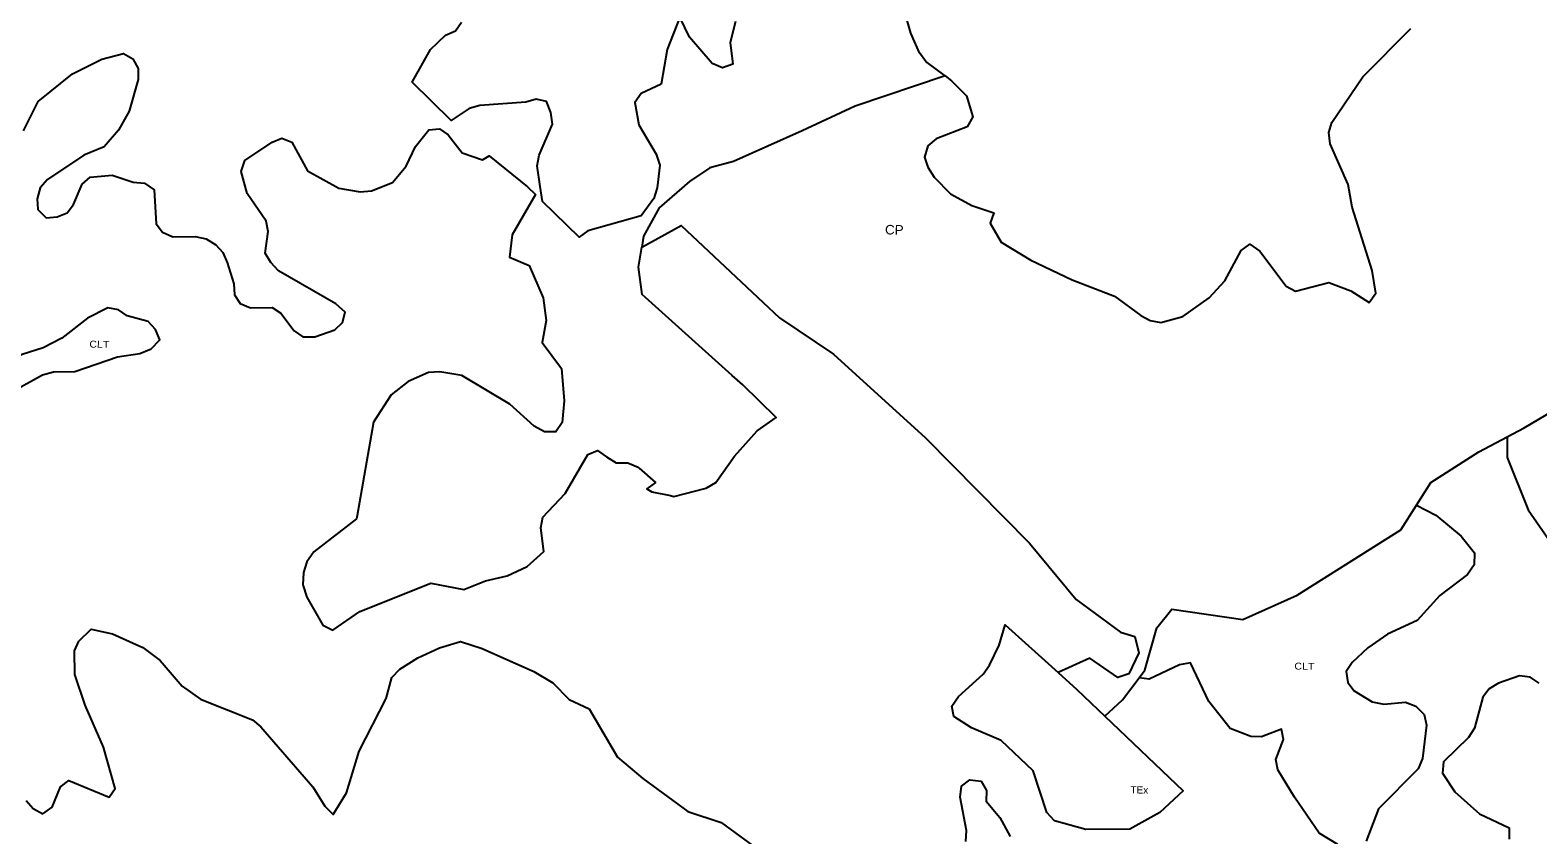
# Model space of a CAD drawing. Extents: x 713589 to 726391, y 7177764 to 7191819.
# Drawn here: x 716445 to 717458, y 7180995 to 7181536 of the extents above; entities that cross this region are included whole.
import ezdxf
from ezdxf.enums import TextEntityAlignment as Align

# ---------------------------------------------------------------- set-up
doc = ezdxf.new("R2010")
doc.units = 0
doc.header["$LTSCALE"] = 2.6
doc.layers.add('63', color=7, linetype='Continuous', lineweight=25)

msp = doc.modelspace()

# ---------------------------------------------------------------- linework, layer by layer
at = {"layer": '63'}
for points in [[(716919.05, 7181541.67), (716915.43, 7181527.52), (716917.07, 7181513.04), (716910.16, 7181510.41), (716903.25, 7181513.37), (716888.12, 7181531.15), (716881.54, 7181544.64), (716872.98, 7181522.92), (716869.03, 7181499.56), (716855.53, 7181493.31), (716851.25, 7181487.06), (716853.88, 7181472.25), (716865.73, 7181452.5), (716868.03, 7181444.93), (716866.38, 7181429.8), (716864.08, 7181422.56), (716855.52, 7181411.04), (716819.65, 7181400.85), (716813.81, 7181396.58), (716789.24, 7181420.53), (716787.69, 7181430.77), (716785.6, 7181444.55), (716786.93, 7181451.81), (716795.87, 7181472.57), (716794.89, 7181480.49), (716791.94, 7181487.76), (716785.01, 7181489.42), (716778.08, 7181487.45), (716747.07, 7181485.19), (716739.81, 7181483.22), (716727.79, 7181474.97), (716701.66, 7181500.8), (716713.81, 7181522.85), (716724.06, 7181532.4), (716730.66, 7181535.36), (716734.63, 7181541.29)], [(717059.92, 7181505.01), (717047.06, 7181514.66), (717042.78, 7181520.59), (717036.86, 7181533.75), (717032.58, 7181548.56)], [(717059.92, 7181505.01), (717064.17, 7181501.83), (717074.36, 7181491.63), (717078.64, 7181477.47), (717074.69, 7181470.89), (717053.96, 7181462.67), (717048.36, 7181458.06), (717046.06, 7181450.5), (717048.36, 7181443.59), (717052.64, 7181437), (717063.49, 7181425.81), (717077.97, 7181417.91), (717092.78, 7181412.97), (717090.15, 7181406.06), (717097.71, 7181393.23), (717117.45, 7181381.05), (717145.42, 7181367.88), (717173.72, 7181357.02), (717191.49, 7181343.85), (717197.74, 7181340.56), (717204.98, 7181339.24), (717219.79, 7181343.19), (717237.56, 7181355.69), (717248.09, 7181367.21), (717258.96, 7181387.61), (717264.88, 7181391.88), (717271.46, 7181387.28), (717289.23, 7181363.58), (717295.48, 7181360.29), (717317.86, 7181366.21), (717332.66, 7181360.61), (717345.17, 7181352.71), (717349.44, 7181358.96), (717347.14, 7181374.1), (717333.66, 7181416.88), (717331.03, 7181432.02), (717318.86, 7181459.33), (717317.87, 7181466.9), (717319.85, 7181473.81), (717340.91, 7181504.41), (717373.17, 7181536.98)], [(716440.24, 7181468.18), (716450.12, 7181487.92), (716473.16, 7181506.34), (716492.9, 7181516.21), (716507.38, 7181520.16), (716513.63, 7181516.54), (716517.25, 7181509.95), (716517.25, 7181502.71), (716511.32, 7181481.33), (716504.08, 7181468.49), (716494.54, 7181457.31), (716480.71, 7181451.71), (716456.36, 7181435.27), (716451.42, 7181429.67), (716449.45, 7181422.43), (716449.78, 7181415.19), (716455.37, 7181409.6), (716462.94, 7181410.25)], [(717059.92, 7181505.01), (716999.53, 7181484.73), (716963.77, 7181468.01), (716917.6, 7181447.53), (716901.79, 7181443.28), (716887.97, 7181434.07), (716867.56, 7181416.3), (716857.03, 7181397.22), (716855.88, 7181389.95)], [(716462.94, 7181410.25), (716469.52, 7181412.89), (716473.8, 7181418.48), (716479.72, 7181432.3), (716484.99, 7181436.91), (716499.8, 7181438.22), (716513.95, 7181433.61), (716521.52, 7181432.95), (716528.1, 7181428.34), (716529.41, 7181405.64), (716533.69, 7181400.04), (716540.6, 7181396.75), (716555.73, 7181397.08), (716562.97, 7181395.43), (716569.55, 7181391.48), (716574.16, 7181386.21), (716577.12, 7181379.63), (716581.72, 7181365.15), (716582.05, 7181357.91), (716586, 7181351.99), (716592.91, 7181349.02), (716607.39, 7181349.35), (716613.31, 7181345.4), (716622.19, 7181333.55), (716628.12, 7181329.6), (716636.01, 7181329.6), (716649.51, 7181334.21), (716654.77, 7181339.14), (716656.42, 7181346.05), (716650.17, 7181351.65), (716611.67, 7181374.03), (716606.41, 7181379.63), (716602.79, 7181385.88), (716604.77, 7181400.36), (716603.45, 7181407.27), (716590.62, 7181426.03), (716586.67, 7181440.84), (716588.98, 7181448.08), (716607.41, 7181460.58), (716613.99, 7181463.21), (716620.57, 7181460.57), (716631.1, 7181441.16), (716652.16, 7181429.64), (716666.64, 7181427), (716674.2, 7181427.66), (716688.36, 7181433.25), (716697.57, 7181444.44), (716703.83, 7181457.6), (716712.71, 7181468.79), (716719.95, 7181469.44), (716725.87, 7181465.49), (716735.09, 7181453.32), (716748.91, 7181448.71), (716753.43, 7181451.35), (716779.05, 7181430.47), (716784.45, 7181425.2), (716768.7, 7181398.07), (716767.02, 7181383.23), (716780.21, 7181377.6), (716789.74, 7181355.81), (716791.69, 7181340.63), (716789.03, 7181325.79), (716801.86, 7181308.29), (716803.81, 7181286.51), (716802.46, 7181272), (716798.17, 7181265.74), (716790.58, 7181265.75), (716783.66, 7181269.39), (716767.19, 7181284.26), (716734.89, 7181303.45), (716720.05, 7181306.11), (716712.46, 7181305.47), (716698.93, 7181299.55), (716687.37, 7181290.66), (716675.46, 7181272.21), (716664.52, 7181209.42), (716664.14, 7181207.24), (716635.4, 7181184.86), (716630.77, 7181178.27), (716628.45, 7181171.02), (716628.11, 7181162.77), (716630.73, 7181154.52), (716641.59, 7181135.7), (716648.18, 7181132.39), (716666.35, 7181144.89), (716714.21, 7181163.95), (716736.3, 7181159.62), (716750.83, 7181165.54), (716765.35, 7181168.81), (716778.88, 7181175.05), (716790.12, 7181185.26), (716788.16, 7181201.1), (716789.49, 7181208.35), (716804.36, 7181224.16)], [(716855.88, 7181389.95), (716882.5, 7181404.46), (716948.63, 7181342.25), (716984.83, 7181317.89), (717046.68, 7181261.61), (717116.76, 7181190.85), (717148.02, 7181153), (717177.96, 7181130.95), (717187.5, 7181127.98), (717190.13, 7181117.12), (717183.55, 7181102.97), (717180.16, 7181101.79), (717175.98, 7181100.34), (717157.22, 7181113.51), (717135.97, 7181103.74)], [(716804.36, 7181224.16), (716819.58, 7181250.53), (716826.18, 7181253.16), (716832.12, 7181248.86), (716838.71, 7181244.89), (716846.62, 7181244.88), (716853.55, 7181241.9), (716854.25, 7181241.28), (716865.26, 7181231.54), (716859.39, 7181227.3), (716862.73, 7181225.25), (716875.19, 7181222.75), (716877.53, 7181222.28), (716899.25, 7181227.87), (716905.84, 7181231.49), (716918.34, 7181249.26), (716933.48, 7181266.37), (716946.33, 7181275.25), (716923.81, 7181297.17), (716916.64, 7181303.63), (716856.2, 7181358.09), (716853.74, 7181376.49), (716855.88, 7181389.95)], [(717437.8, 7181262.38), (717449.33, 7181268.45), (717489.81, 7181292.46), (717596.72, 7181346.37)], [(717376.94, 7181216.44), (717386.48, 7181231.6), (717418.73, 7181252.33), (717437.8, 7181262.38)], [(717437.8, 7181262.38), (717437.95, 7181248.38), (717452.09, 7181213.17), (717485.97, 7181164.13)], [(717190.46, 7181100.3), (717194.28, 7181105.28), (717202.18, 7181133.9), (717212.38, 7181146.41), (717260.1, 7181139.49), (717296.63, 7181155.93), (717366.4, 7181199.69), (717376.94, 7181216.44)], [(717376.94, 7181216.44), (717389.89, 7181209.56), (717407, 7181195.4), (717415.89, 7181184.21), (717415.56, 7181176.32), (717411.28, 7181169.73), (717392.52, 7181155.59), (717377.38, 7181138.81), (717357.3, 7181129.6), (717344.14, 7181120.39), (717333.61, 7181110.52), (717329.66, 7181104.59), (717330.64, 7181097.02), (717334.92, 7181091.43), (717347.09, 7181084.19), (717354.99, 7181082.54), (717369.47, 7181083.85), (717376.38, 7181081.22), (717381.97, 7181075.63), (717383.62, 7181068.39), (717380.98, 7181046.01), (717378.02, 7181039.1), (717351.36, 7181012.12), (717343.13, 7180990.4)], [(717167.37, 7181074.45), (717219.98, 7181024.17), (717204.26, 7181009.65), (717184.19, 7180998.46), (717154.57, 7180998.14), (717133.51, 7181004.06), (717128.25, 7181009.66), (717119.04, 7181037.63), (717097.65, 7181058.04), (717077.58, 7181066.6), (717065.74, 7181074.17), (717064.42, 7181081.08), (717069.03, 7181087.66), (717085.49, 7181102.79), (717089.76, 7181108.72), (717096.35, 7181122.21), (717100.26, 7181135.84), (717135.97, 7181103.74)], [(716441.9, 7181017.81), (716446.79, 7181012.33), (716453.09, 7181008.67), (716459.39, 7181013.3), (716465.05, 7181026.88), (716470.69, 7181031.18), (716497.84, 7181019.86), (716501.83, 7181025.82), (716493.92, 7181053.67), (716481.71, 7181081.86), (716474.78, 7181102.42), (716474.48, 7181118.33), (716477.47, 7181124.96), (716485.71, 7181132.99), (716500.07, 7181129.88), (716520.47, 7181120.66), (716531.99, 7181111.78), (716546.8, 7181094.66), (716559.3, 7181085.77), (716594.18, 7181071.95), (716599.77, 7181067.34), (716634.65, 7181026.86), (716642.87, 7181014.02)], [(716642.87, 7181014.02), (716648.36, 7181008.26), (716653.8, 7181017.12), (716657.35, 7181022.9), (716665.91, 7181050.87), (716684.02, 7181086.41), (716687.97, 7181100.56), (716693.23, 7181106.15), (716705.41, 7181113.72), (716719.89, 7181120.3), (716734.04, 7181124.57), (716748.52, 7181119.96), (716783.4, 7181104.49), (716796.23, 7181096.92), (716807.09, 7181085.73), (716820.58, 7181079.48), (716839.66, 7181046.89), (716856.77, 7181032.41), (716886.95, 7181010.24), (716909.28, 7181002.98), (716946.13, 7180975.99)], [(717324.04, 7180988.1), (717311.54, 7180995.67), (717294.76, 7181020.03), (717283.57, 7181038.46), (717282.26, 7181045.37), (717287.53, 7181058.86), (717286.21, 7181065.77), (717272.72, 7181060.51), (717265.48, 7181060.84), (717251.66, 7181066.11), (717237.18, 7181084.21), (717225.01, 7181110.21), (717217.44, 7181108.89), (717197.04, 7181099.35), (717190.46, 7181100.3)], [(717135.97, 7181103.74), (717148.53, 7181092.45), (717167.37, 7181074.45)], [(717167.37, 7181074.45), (717179.14, 7181085.53), (717190.46, 7181100.3)], [(717459.31, 7181096.67), (717453.39, 7181100.62), (717446.15, 7181101.61), (717432, 7181096.68), (717425.74, 7181092.73), (717421.46, 7181087.14), (717415.87, 7181066.41), (717411.92, 7181060.15), (717395.13, 7181043.7), (717394.47, 7181036.14), (717402.7, 7181023.63), (717419.15, 7181008.82), (717439.22, 7180999.27), (717439.22, 7180991.7)], [(717073.95, 7180990.25), (717074.28, 7180997.49), (717070, 7181019.87), (717070.99, 7181027.44), (717076.59, 7181031.72), (717084.16, 7181030.73), (717087.77, 7181024.47), (717087.44, 7181017.23), (717096.66, 7181006.37), (717103.56, 7180993.54)]]:
    msp.add_lwpolyline(points, dxfattribs=at)
msp.add_lwpolyline([(716422.11, 7181303.97), (716420.8, 7181297.06), (716427.05, 7181293.77), (716434.29, 7181293.77), (716453.05, 7181303.97), (716460.29, 7181305.94), (716474.77, 7181306.27), (716503.4, 7181316.13), (716518.53, 7181318.43), (716526.1, 7181321.39), (716531.89, 7181327.52), (716529.07, 7181334.56), (716524.13, 7181339.82), (716509.98, 7181343.77), (716504.06, 7181347.72), (716496.82, 7181349.04), (716483.33, 7181342.13), (716465.89, 7181328.64), (716453.38, 7181322.07), (716439.23, 7181317.79), (716426.39, 7181311.54)], close=True, dxfattribs=at)

# ---------------------------------------------------------------- texts
for s, height, width, p in [('CP', 6.4, 1.05, (717025.72, 7181398.37)), ('CLT', 4.64, 1.15, (716491.16, 7181322.25)), ('CLT', 4.64, 1.15, (717301.47, 7181105.69)), ('TEx', 4.8, 1.05, (717190.48, 7181022.43))]:
    msp.add_text(s, height=height, rotation=359.062, dxfattribs=dict(at, width=width)).set_placement(p, align=Align.CENTER)

doc.saveas('drawing.dxf')
